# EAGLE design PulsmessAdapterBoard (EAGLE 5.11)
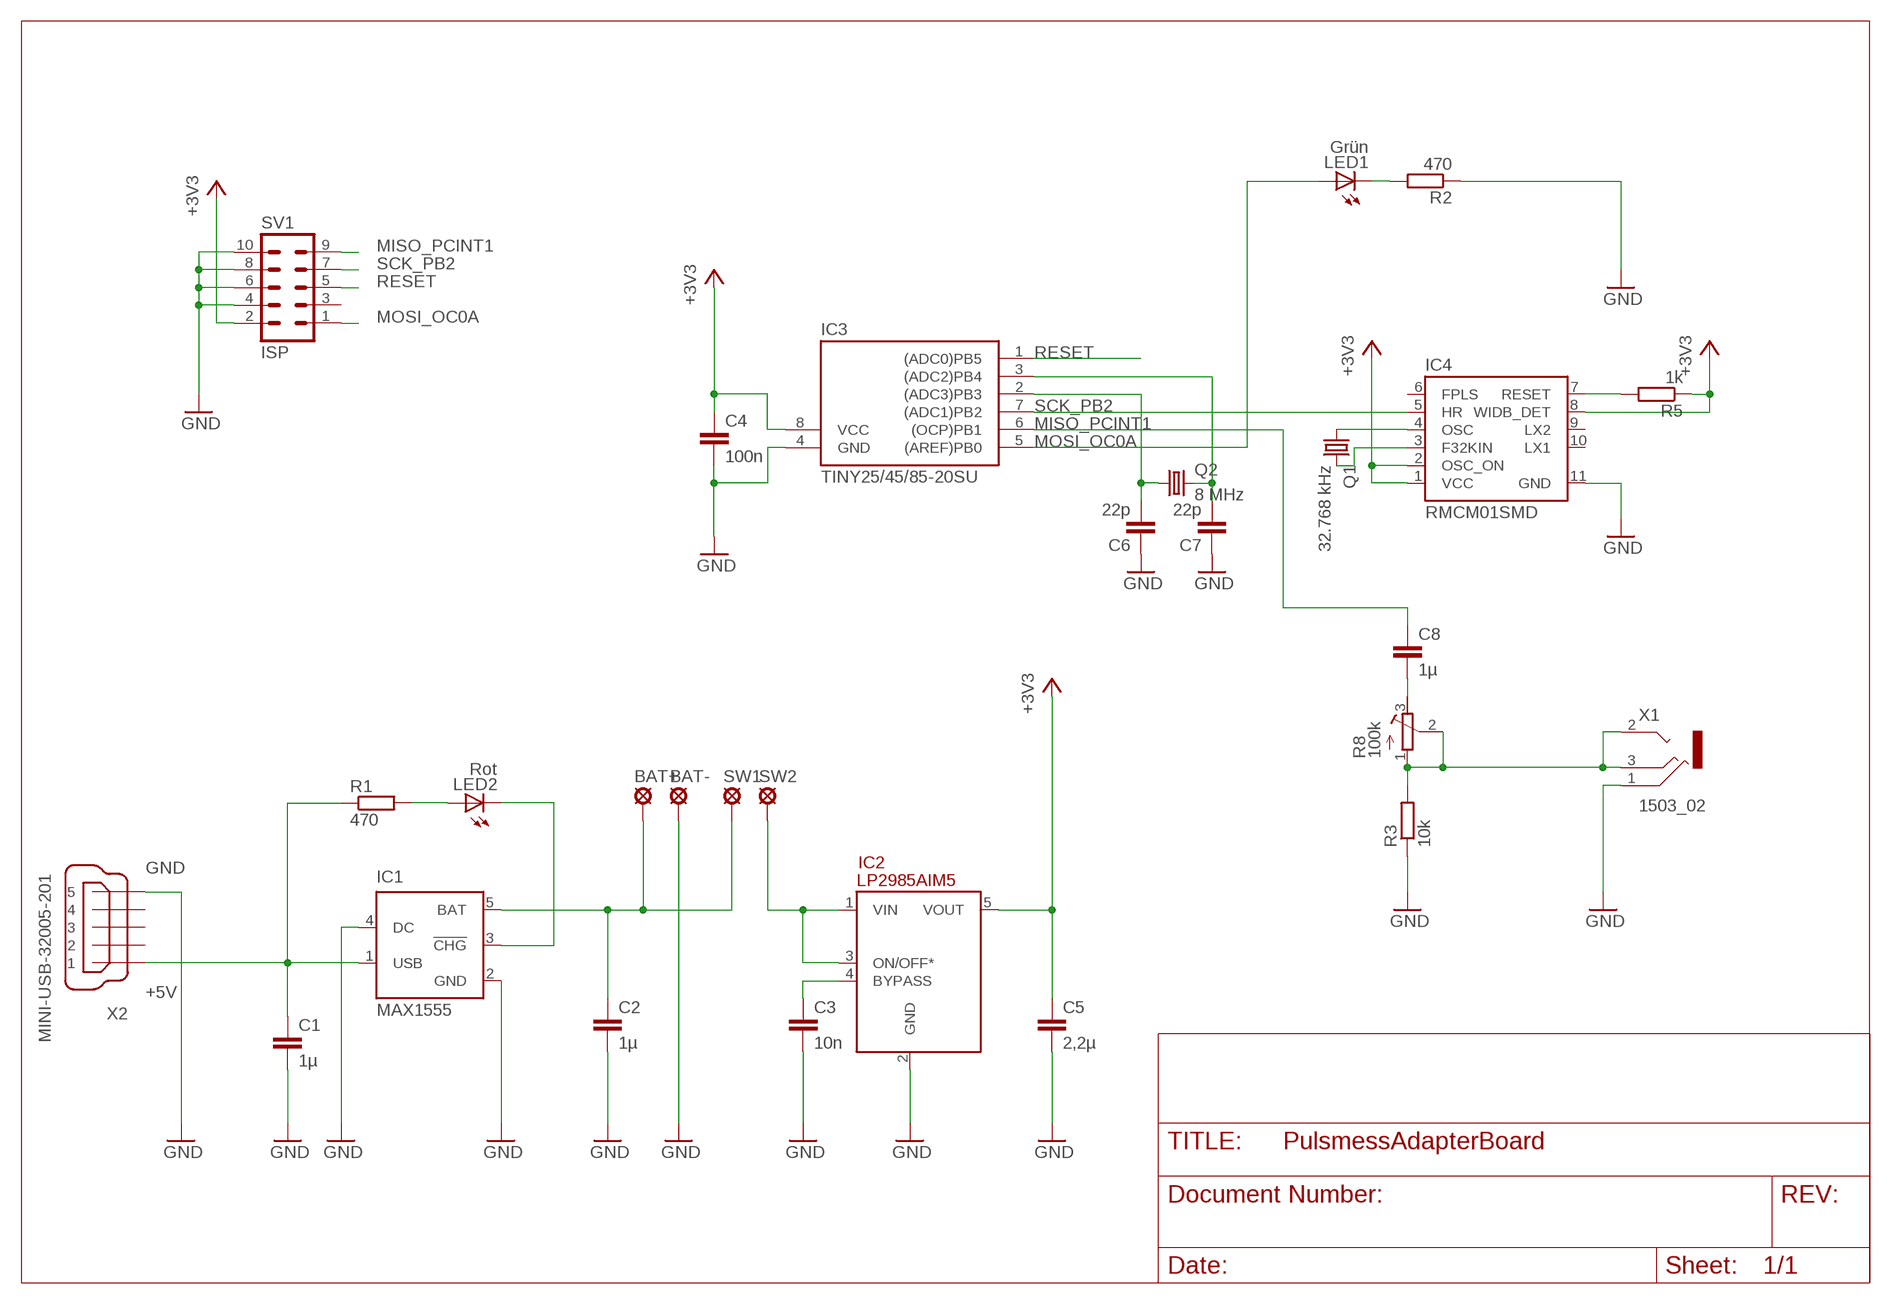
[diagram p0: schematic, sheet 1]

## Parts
BAT+  LSP13  [LSP13]
BAT-  LSP13  [LSP13]
C1  1µ  C-EUC0805  [C0805]
C2  1µ  C-EUC0805  [C0805]
C3  10n  C-EUC0805  [C0805]
C4  100n  C-EUC0805  [C0805]
C5  2,2µ  C-EUC0805  [C0805]
C6  22p  C-EUC0805  [C0805]
C7  22p  C-EUC0805  [C0805]
C8  1µ  C-EUC0805  [C0805]
IC1  MAX1555  [SOT23-5L]
IC2  LP2985AIM5  [SOT23-5L]
IC3  TINY25/45/85-20SU  [SOIC8]
IC4  RMCM01SMD  [RMCM01]
LED1  Grün  LEDCHIPLED_1206  [CHIPLED_1206]
LED2  Rot  LEDCHIPLED_1206  [CHIPLED_1206]
Q1  32.768 kHz  CRYSTALTC38H  [TC38H]
Q2  8 MHz  CRYSTALHC49UP  [HC49UP]
R1  470  R-EU_R0805  [R0805]
R2  470  R-EU_R0805  [R0805]
R3  10k  R-EU_R0805  [R0805]
R5  1k  R-EU_R0805  [R0805]
R8  100k  R-TRIMM3339P  [RTRIM3339P]
SV1  ISP  ML10  [ML10]
SW1  LSP13  [LSP13]
SW2  LSP13  [LSP13]
X1  1503_02  [1503_02]
X2  MINI-USB-32005-201  [32005-201]

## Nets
+3V3: C4.1 C5.1 IC2.5(VOUT) IC3.8(VCC) IC4.1(VCC) IC4.2(OSC_ON) IC4.8(WIDB_DET) R5.1 SV1.2
+5V: C1.1 IC1.1(USB) R1.1 X2.1
BAT: BAT+.MP C2.1 IC1.5(BAT) SW1.MP
GND: BAT-.MP C1.2 C2.2 C3.2 C4.2 C5.2 C6.1 C7.1 IC1.2(GND) IC1.4(DC) IC2.2(GND) IC3.4(GND) IC4.11(GND) R2.1 R3.1 SV1.4 SV1.6 SV1.8 SV1.10 X1.1 X2.5
MISO_PCINT1: C8.1 IC3.6((OCP)PB1) SV1.9
MOSI_OC0A: IC3.5((AREF)PB0) LED1.A SV1.1
N$1: IC2.1(VIN) IC2.3(ON/OFF*) SW2.MP
N$2: C3.1 IC2.4(BYPASS)
N$3: IC1.3(!CHG) LED2.C
N$4: LED2.A R1.2
N$5: C8.2 R8.3(A)
N$6: C6.2 IC3.2((ADC3)PB3) Q2.1
N$7: C7.2 IC3.3((ADC2)PB4) Q2.2
N$9: LED1.C R2.2
N$11: R3.2 R8.1(E) R8.2(S) X1.2 X1.3
N$13: IC4.7(RESET) R5.2
N$14: IC4.4(OSC) Q1.1
N$15: IC4.3(F32KIN) Q1.2
RESET: IC3.1((ADC0)PB5) SV1.5
SCK_PB2: IC3.7((ADC1)PB2) IC4.5(HR) SV1.7
Unconnected: IC4.6(FPLS) IC4.9(LX2) IC4.10(LX1) SV1.3 X1.2@2 X2.2 X2.3 X2.4

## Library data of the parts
BAT+ BAT- SW1 SW2 = solpad:LSP13: SOLDER PAD
C1-C8 = rcl:C-EU: CAPACITOR, European symbol
IC1 = maxim:MAX1555: Dual-Input USB/AC Adapter 1-Cell Li+ Battery Chargers Source: http://www.maxim-ic.com .. MAX1551-MAX1555.pdf; MF: MAXIM; MPN: MAX1555EZK+T; OC_FARNELL: 1628222; OC_NEWARK: 59J2761
IC2 = 0-svo-lp2981:LP2985*: Micropower 150 mA Low-Noise Ultra Low-Dropout Regulator in SOT-23 and micro SMD Packages Designed for Use with Very Low ESR Output Capacitors
IC3 = avr-6:TINY25/45/85
IC4 = SparkFun:RMCM01
LED1 LED2 = led:LED: LED
Q1 Q2 = crystal:CRYSTAL: CRYSTAL; OC_FARNELL: unknown; OC_NEWARK: unknown
R1-R3 R5 = rcl:R-EU_: RESISTOR, European symbol
R8 = rcl:R-TRIMM: Trimm resistor
SV1 = con-harting-ml:ML10: HARTING; OC_FARNELL: unknown; OC_NEWARK: unknown
X1 = con-lumberg:1503_02: Jack connectors according to JISC 6560, 3.5 mm Klinkeneinbaukupplung nach JISC 6560, 3,5 mm, 3-polig/stereo, abgewinkelte Ausführung, Surface-Mount-Technik (SMT) Source: http://www.lumberg.com/Produkte/PDFs/1503_02.pdf; OC_FARNELL: 1216979; OC_NEWARK: unknown
X2 = con-cypressindustries:MINI-USB-: MINI USB-B Conector Source: www.cypressindustries.com; OC_FARNELL: unknown; OC_NEWARK: unknown

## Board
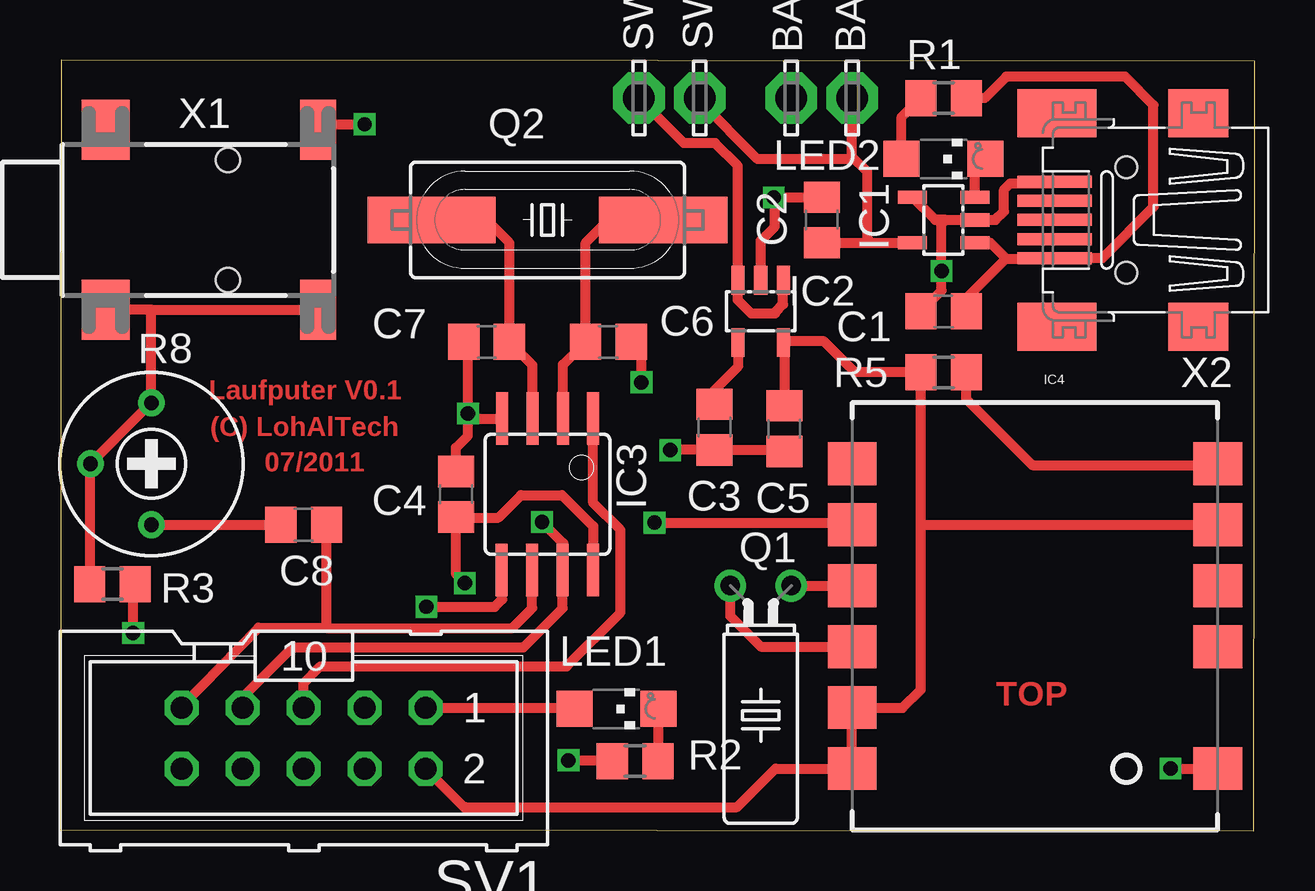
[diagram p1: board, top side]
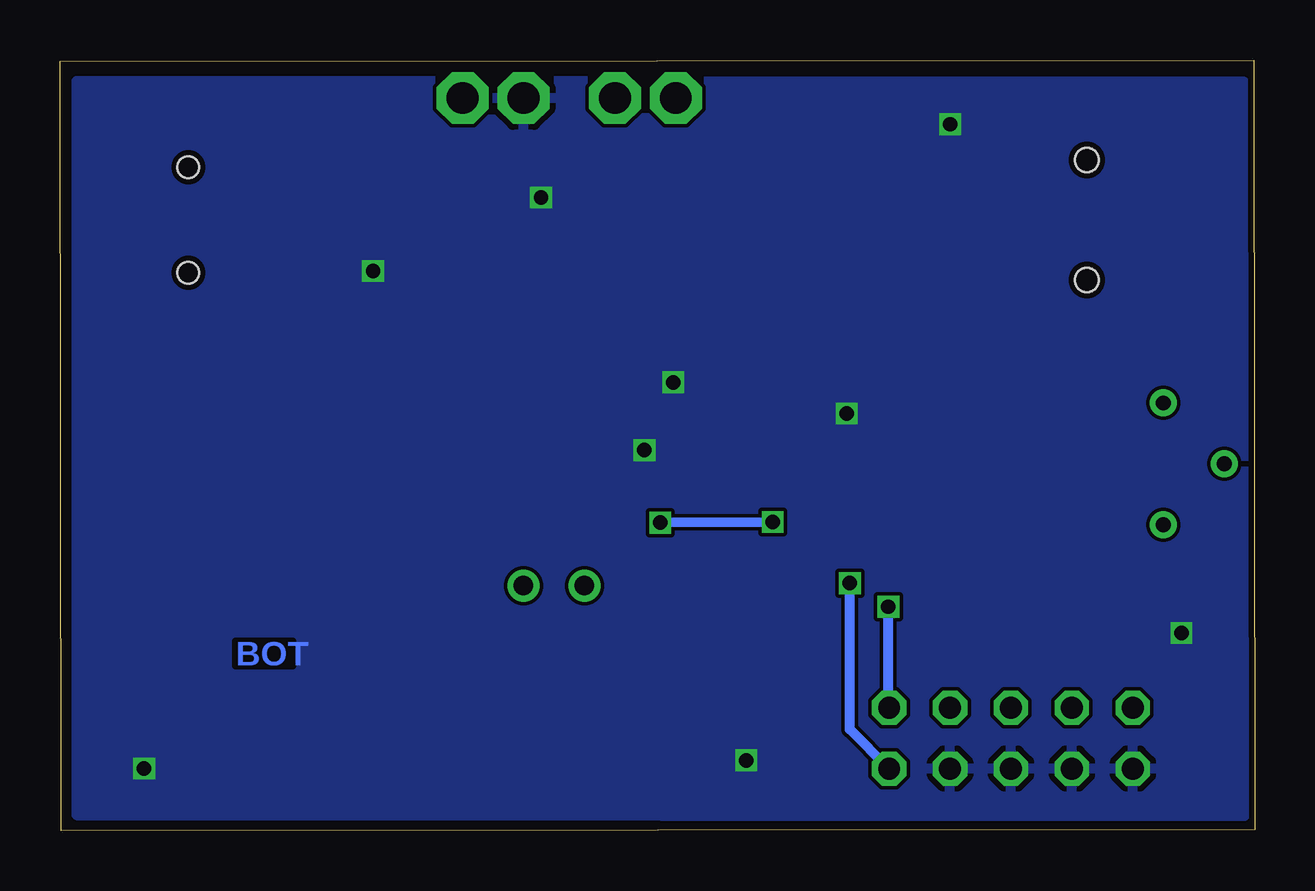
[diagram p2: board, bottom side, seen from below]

Size 49.8 x 32.11 mm. Coordinates in mm from the lower left corner, seen from the top.
Outline: 0,0.05 49.76,0 49.8,32.06 0.05,32.11 0,0.05
Copper layers (1*16): Top 0.035mm / dielectric 1.5mm / Bottom 0.035mm
Design rules "ITead_rule": minimum track width 6mil, minimum drill 12mil, track to track 6mil, track to pad 6mil, pad to pad 6mil, via to via 6mil, smd to smd 0mil, copper to edge 10mil, drill to drill 10mil, minimum pad ring 10mil, minimum via ring 6mil, stop-mask expansion 2mil, vias tented up to drill 100mil, thermal gap 10mil

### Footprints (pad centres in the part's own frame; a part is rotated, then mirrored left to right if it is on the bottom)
LSP13 = drill 1.321 pad 2.159 octagon: MP 0,0
C0805 = smd 1.3 x 1.5: 1 -0.95,0; 2 0.95,0
SOT23-5L = smd 0.55 x 1.2: 1 -0.95,-1.3; 2 0,-1.3; 3 0.95,-1.3; 4 0.95,1.3; 5 -0.95,1.3
SOIC8 = smd 0.5 x 2.2: 1 -1.905,-3.154; 2 -0.645,-3.154; 3 0.625,-3.154; 4 1.895,-3.154; 5 1.905,3.154; 6 0.635,3.154; 7 -0.635,3.154; 8 -1.905,3.154
RMCM01 = smd 1.778 x 2.032: 1 -6.35,7.62; 2 -3.81,7.62; 3 -1.27,7.62; 4 1.27,7.62; 5 3.81,7.62; 6 6.35,7.62; 7 6.35,-7.62; 8 3.81,-7.62; 9 1.27,-7.62; 10 -1.27,-7.62; 11 -6.35,-7.62
CHIPLED_1206 = smd 1.5 x 1.5: A 0,-1.75; C 0,1.75
TC38H = drill 0.813 round: 1 -1.27,0; 2 1.27,0
HC49UP = smd 5.334 x 1.93: 1 -4.826,0; 2 4.826,0
R0805 = smd 1.3 x 1.5: 1 -0.95,0; 2 0.95,0
RTRIM3339P = drill 0.61 round: 1 -2.54,0; 2 0,-2.54; 3 2.54,0
ML10 = drill 0.914 octagon: 1 -5.08,-1.27; 2 -5.08,1.27; 3 -2.54,-1.27; 4 -2.54,1.27; 5 0,-1.27; 6 0,1.27; 7 2.54,-1.27; 8 2.54,1.27; 9 5.08,-1.27; 10 5.08,1.27
1503_02 = smd 2.5 x 1.5: 1 3.75,-10.75; 3 -3.75,-10.75 | smd 2.5 x 2: 2 -3.75,-1.9; 2@2 3.75,-1.9 | hole 1: -2.5,-7; 2.5,-7
32005-201 = smd 3.1 x 0.5: 1 3,1.6; 2 3,0.8; 3 3,0; 4 3,-0.8; 5 3,-1.6 | smd 2.5 x 2: M1 -3,-4.45; M2 -3,4.45 | smd 3.3 x 2: M3 2.9,4.45; M4 2.9,-4.45 | hole 0.9: 0,2.2; 0,-2.2

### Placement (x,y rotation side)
BAT+  33.02,30.53 90 top
BAT-  30.48,30.53 90 top
C1  36.83,21.64 180 top
C2  31.75,25.45 90 top
C3  27.28,16.81 270 top
C4  16.51,14.02 90 top
C5  30.19,16.75 270 top
C6  22.86,20.37 180 top
C7  17.78,20.37 0 top
C8  10.16,12.75 180 top
IC1  36.83,25.45 90 top
IC2  29.21,21.64 180 top
IC3  20.32,14.02 180 top
IC4  40.64,8.94 90 top
LED1  23.19,5.07 270 top
LED2  36.83,27.99 270 top
Q1  29.21,10.21 180 top
Q2  20.32,25.45 180 top
R1  36.83,30.53 180 top
R2  23.97,2.9 0 top
R3  2.19,10.27 180 top
R5  36.83,19.1 0 top
R8  3.81,15.29 270 top
SV1  10.16,3.86 180 top
SW1  26.67,30.53 90 top
SW2  24.13,30.53 90 top
X1  0,25.45 90 top
X2  44.45,25.45 180 top

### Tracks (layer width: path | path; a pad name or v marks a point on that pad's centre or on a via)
+3V3  (via drill 0.6)
  Top 0.406: IC2.5 30.21,20.38 31.85,20.38 33.13,19.1 R5.1 35.88,12.75 | IC2.5 30.21,20.29 | C5.1 30.19,20.31 IC2.5 | v16.88,10.31 16.52,10.67 C4.1 16.53,13.05 18.27,13.05 19.21,13.99 20.93,13.99 22.23,12.69 IC3.8 | SV1.2 16.86,0.96 16.89,0.98 28.22,0.98 29.83,2.59 IC4.1 IC4.2 33.03,5.11 35.12,5.11 35.88,5.87 35.88,12.75 | IC4.8 35.89,12.75 35.88,12.75
  Bottom 0.406: v16.88,10.31 16.88,4.23 SV1.2
+5V
  Top 0.406: IC1.1 38.78,24.5 39.38,23.9 39.38,23.86 39.42,23.82 | 39.42,23.82 41.43,23.82 X2.1 41.48,23.87 43.46,23.87 45.58,25.99 45.58,30.24 44.4,31.42 39.44,31.42 38.55,30.53 R1.1 | C1.1 37.78,22.18 39.42,23.82
BAT
  Top 0.406: C2.1 33.81,24.5 | 33.81,24.5 IC1.5 | 33.02,28.09 BAT+.MP | 33.02,28.09 33.65,27.46 33.65,24.66 33.81,24.5 | SW1.MP 26.67,30.39 29.08,27.98 32.91,27.98 33.02,28.09
GND  (via drill 0.6)
  Top 0.406: X2.5 41.37,26.97 39.61,26.97 39.35,26.71 39.35,25.79 39,25.45 IC1.2 36.93,25.45 | 36.93,25.45 36.48,25.45 IC1.4 | C5.2 30.13,15.86 C3.2 25.45,15.86 v25.44,15.85 | C4.2 16.51,15.96 17.01,16.46 v17.01,17.38 | IC3.4 17.22,17.17 v17.01,17.38 | v17.01,17.38 17.01,20.19 C7.1 | IC4.11 v46.3,2.59 v46.3,2.6 | v24.24,18.68 24.24,19.94 C6.1 | 36.93,25.45 36.75,25.26 v36.75,23.32 36.75,22.51 C1.2 | C2.2 29.77,26.4 v29.75,26.38 29.8,26.33 29.8,25.17 29.21,24.58 IC2.2 | v12.7,29.44 10.99,29.44 X1.1 | v3.05,8.24 3.05,10.18 R3.1 | v21.19,2.93 23.02,2.93 R2.1
  pour Bottom: 0.42,31.2 49.12,31.24 49.12,0.65 0.42,0.6
MISO_PCINT1
  Top 0.406: IC3.6 19.68,9.28 18.84,8.43 11.16,8.43 11.11,8.48 | SV1.9 5.13,5.18 5.13,5.22 8.28,8.46 10.97,8.46 11.11,8.48 | 11.11,8.48 C8.1
MOSI_OC0A  (via drill 0.6)
  Top 0.406: v15.27,9.33 18.12,9.33 18.43,9.63 18.43,10.85 IC3.5 | SV1.1 21.39,5.13 LED1.A
  Bottom 0.406: v15.27,9.33 15.27,5.16 SV1.1
N$1
  Top 0.406: IC2.1 30.14,22.92 30.14,21.93 29.82,21.61 29.82,21.54 28.82,21.54 28.26,22.1 IC2.3 28.26,27.7 27.31,28.65 26,28.65 SW2.MP
N$2
  Top 0.406: C3.1 27.28,18.36 28.28,19.35 28.28,20.32 IC2.4
N$3
  Top 0.406: IC1.3 38.13,27.54 LED2.C
N$4
  Top 0.406: LED2.A 35.08,29.73 R1.2
N$5
  Top 0.406: R8.3 C8.2
N$6
  Top 0.406: IC3.2 20.96,19.42 C6.2 21.91,24.5 22.86,25.45 Q2.1
N$7
  Top 0.406: IC3.3 19.7,19.4 C7.2 18.73,24.5 17.78,25.45 Q2.2
N$9
  Top 0.406: R2.2 24.94,2.9 LED1.C
N$10
  Top 0.406: 22.97,2.9 22.97,2.91
N$11
  Top 0.406: 3.86,21.7 X1.2 | 3.86,21.7 X1.3 | 3.86,21.7 3.81,21.65 R8.1 R8.2 1.27,10.3 R3.2 1.54,10.25
N$13
  Top 0.406: R5.2 37.78,17.98 40.53,15.23 48.21,15.23 IC4.7
N$14
  Top 0.406: Q1.1 IC4.4
N$15
  Top 0.406: Q1.2 27.94,8.94 29.21,7.67 IC4.3
N$17
  Top 0.406: 24.93,2.86 24.89,2.86
RESET
  Top 0.406: IC3.1 22.23,13.66 23.36,12.53 23.36,9.09 21.12,6.85 10.85,6.85 10.15,6.15 SV1.5
SCK_PB2  (via drill 0.6)
  Top 0.406: SV1.7 7.68,5.19 7.68,5.63 9.69,7.64 19.32,7.64 20.95,9.27 IC3.7 20.98,10.89 20.98,11.98 v20.09,12.86 | v24.78,12.83 32.93,12.83 IC4.5
  Bottom 0.406: v20.09,12.86 v24.78,12.83 | v24.78,12.83

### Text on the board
Top: Laufputer V0.1 | (C) LohAlTech | 07/2011 | TOP
Bottom: BOT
